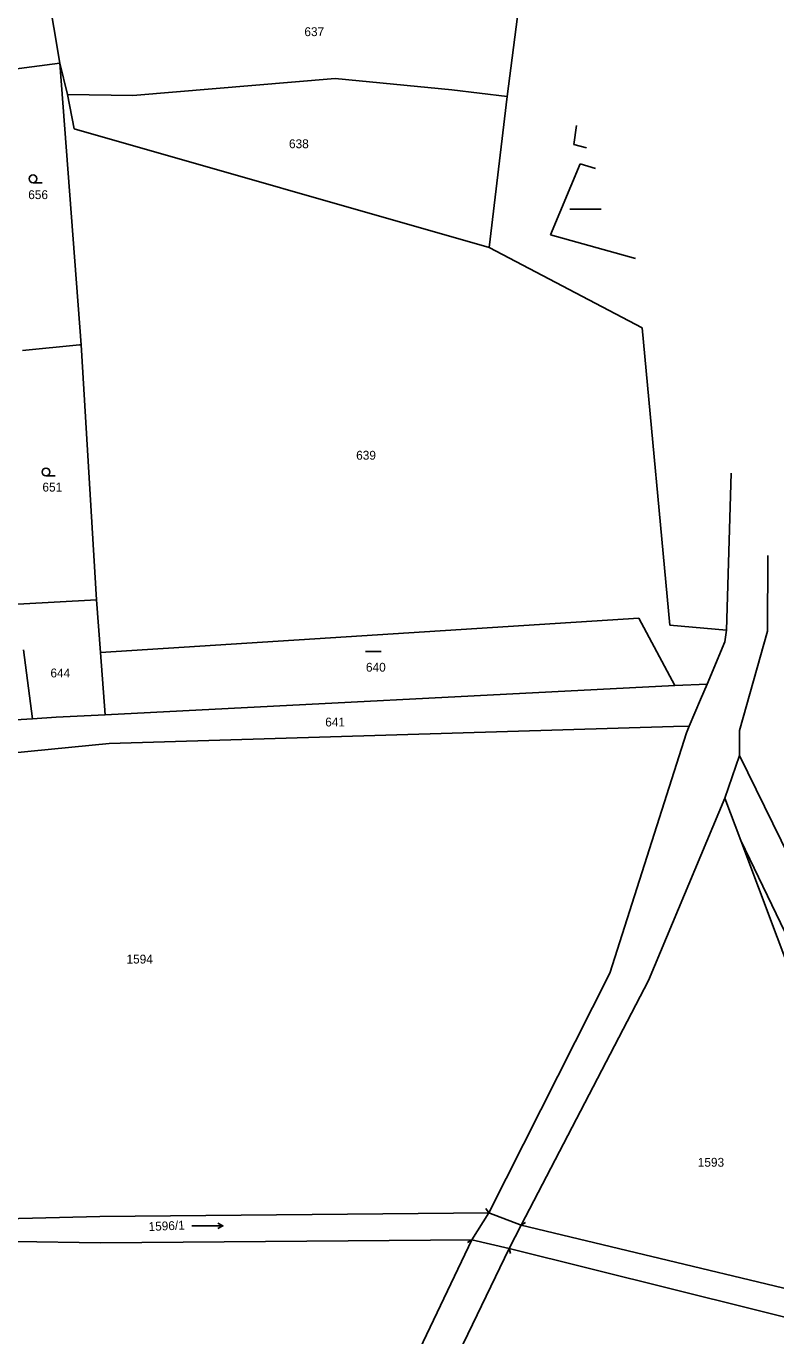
# Model space of a CAD drawing. Extents: x -779596 to -776743, y -1030330 to -1024513.
# Drawn here: x -777678.9 to -777535.2, y -1025297.1 to -1025045.8 of the extents above; entities that cross this region are included whole.
import ezdxf

# ---------------------------------------------------------------- set-up
doc = ezdxf.new("R2010")
doc.units = 0
for name, color, linetype in [('hranice parcel', 7, 'Continuous'), ('hranice vnitřní', 7, 'Continuous'), ('kultura', 7, 'Continuous'), ('Vrstva 26', 7, 'Continuous'), ('č_ parcel šipka', 7, 'Continuous'), ('č_parcel poz_', 7, 'Continuous')]:
    doc.layers.add(name, color=color, linetype=linetype)

msp = doc.modelspace()

# ---------------------------------------------------------------- linework, layer by layer
at = {"layer": 'hranice parcel'}
for points in [[(-777675.84, -1025032.7), (-777672.5, -1025052.88)], [(-777586.68, -1025059.33), (-777584.262, -1025040.422)], [(-777685.71, -1025054.61), (-777672.5, -1025052.88)], [(-777672.5, -1025052.88), (-777668.37, -1025106.96)], [(-777672.5, -1025052.88), (-777671, -1025058.9)], [(-777658.48, -1025059.11), (-777619.65, -1025055.84)], [(-777619.65, -1025055.84), (-777597.29, -1025058.06)], [(-777671, -1025058.9), (-777658.48, -1025059.11)], [(-777671, -1025058.9), (-777669.7, -1025065.5)], [(-777597.29, -1025058.06), (-777586.68, -1025059.33)], [(-777590.13, -1025088.29), (-777586.68, -1025059.33)], [(-777573.9, -1025068.5), (-777573.4, -1025064.86)], [(-777669.7, -1025065.5), (-777590.13, -1025088.29)], [(-777573.9, -1025068.5), (-777571.497, -1025069.141)], [(-777578.38, -1025085.88), (-777572.67, -1025072.23)], [(-777572.67, -1025072.23), (-777569.727, -1025073.124)], [(-777578.38, -1025085.88), (-777562.061, -1025090.372)], [(-777590.13, -1025088.29), (-777560.83, -1025103.69)], [(-777560.83, -1025103.69), (-777555.53, -1025160.78)], [(-777679.64, -1025108.07), (-777668.73, -1025106.99)], [(-777668.73, -1025106.99), (-777668.37, -1025106.96)], [(-777668.37, -1025106.96), (-777665.41, -1025155.9)], [(-777544.65, -1025161.75), (-777543.74, -1025131.593)], [(-777536.76, -1025161.91), (-777536.709, -1025147.411)], [(-777680.55, -1025156.71), (-777665.41, -1025155.9)], [(-777665.41, -1025155.9), (-777664.66, -1025165.98)], [(-777664.66, -1025165.98), (-777561.44, -1025159.43)], [(-777561.44, -1025159.43), (-777554.56, -1025172.37)], [(-777555.53, -1025160.78), (-777544.65, -1025161.75)], [(-777544.97, -1025163.97), (-777544.65, -1025161.75)], [(-777542.15, -1025180.96), (-777536.76, -1025161.91)], [(-777679.42, -1025165.49), (-777677.72, -1025178.71)], [(-777548.37, -1025172.06), (-777544.97, -1025163.97)], [(-777664.66, -1025165.98), (-777663.76, -1025177.95)], [(-777663.76, -1025177.95), (-777554.56, -1025172.37)], [(-777554.56, -1025172.37), (-777548.37, -1025172.06)], [(-777549.63, -1025175.06), (-777548.37, -1025172.06)], [(-777551.77, -1025180.15), (-777549.63, -1025175.06)], [(-777677.72, -1025178.71), (-777673.2, -1025178.43)], [(-777673.2, -1025178.43), (-777663.76, -1025177.95)], [(-777696.22, -1025179.85), (-777677.72, -1025178.71)], [(-777663, -1025183.5), (-777554.77, -1025180.24)], [(-777554.77, -1025180.24), (-777551.77, -1025180.15)], [(-777552.31, -1025181.44), (-777551.77, -1025180.15)], [(-777542.17, -1025185.78), (-777542.15, -1025180.96)], [(-777567, -1025227.56), (-777552.31, -1025181.44)], [(-777720.94, -1025189.16), (-777663, -1025183.5)], [(-777544.93, -1025193.94), (-777542.17, -1025185.78)], [(-777542.17, -1025185.78), (-777487.94, -1025296.43)], [(-777559.62, -1025228.95), (-777544.93, -1025193.94)], [(-777544.93, -1025193.94), (-777541.87, -1025202.11)], [(-777541.87, -1025202.11), (-777507.26, -1025294.32)], [(-777541.87, -1025202.11), (-777496.94, -1025295.45)], [(-777590.23, -1025273.53), (-777567, -1025227.56)], [(-777584.01, -1025275.89), (-777559.62, -1025228.95)], [(-777664.83, -1025274.27), (-777590.23, -1025273.53)], [(-777590.23, -1025273.53), (-777584.01, -1025275.89)], [(-777729.5, -1025275.83), (-777664.83, -1025274.27)], [(-777584.01, -1025275.89), (-777507.26, -1025294.32)], [(-777729.93, -1025278.29), (-777664.67, -1025279.31)], [(-777664.67, -1025279.31), (-777593.48, -1025278.7)], [(-777626.86, -1025348.73), (-777593.48, -1025278.7)], [(-777593.48, -1025278.7), (-777586.28, -1025280.38)], [(-777620.65, -1025351.61), (-777586.28, -1025280.38)], [(-777586.28, -1025280.38), (-777508.04, -1025299.92)]]:
    msp.add_lwpolyline(points, dxfattribs=at)
at = {"layer": 'hranice vnitřní'}
for points in [[(-777593.48, -1025278.7), (-777590.23, -1025273.53)], [(-777586.28, -1025280.38), (-777584.01, -1025275.89)]]:
    msp.add_lwpolyline(points, dxfattribs=at)
at = {"layer": 'kultura'}
for points in [[(-777677.61, -1025075.85), (-777675.86, -1025075.85)], [(-777574.68, -1025080.93), (-777568.68, -1025080.93)], [(-777675.13, -1025132.13), (-777673.38, -1025132.13)], [(-777613.85, -1025165.85), (-777610.85, -1025165.85)], [(-777647.19, -1025276.05), (-777641.19, -1025276.05)], [(-777642.19, -1025275.55), (-777641.19, -1025276.05), (-777642.19, -1025276.55)]]:
    msp.add_lwpolyline(points, dxfattribs=at)
for centre in [(-777677.61, -1025075.1), (-777675.13, -1025131.38)]:
    msp.add_circle(centre, 0.75, dxfattribs=at)
at = {"layer": 'Vrstva 26'}
for points in [[(-777590.758, -1025272.694), (-777590.23, -1025273.53)], [(-777583.149, -1025275.403), (-777584.01, -1025275.89)], [(-777594.319, -1025279.224), (-777593.48, -1025278.7)], [(-777586.051, -1025281.342), (-777586.28, -1025280.38)]]:
    msp.add_lwpolyline(points, dxfattribs=at)

# ---------------------------------------------------------------- texts
at = {"layer": 'č_ parcel šipka'}
msp.add_text('1596/1', height=1.7, rotation=2.40002, dxfattribs=at).set_placement((-777655.429, -1025277.042))
at = {"layer": 'č_parcel poz_'}
for s, p in [('637', (-777625.58, -1025047.72)), ('638', (-777628.53, -1025069.23)), ('656', (-777678.53, -1025079)), ('639', (-777615.65, -1025129.01)), ('651', (-777675.81, -1025135.12)), ('640', (-777613.77, -1025169.69)), ('644', (-777674.27, -1025170.79)), ('641', (-777621.58, -1025180.21)), ('1594', (-777659.69, -1025225.7)), ('1593', (-777550.15, -1025264.7))]:
    msp.add_text(s, height=1.7, dxfattribs=at).set_placement(p)

doc.saveas('drawing.dxf')
